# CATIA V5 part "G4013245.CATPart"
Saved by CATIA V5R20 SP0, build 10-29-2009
Part number: G4013245
Revision: 6
Definition: design
Nomenclature: G4013245
Source: made
Description: NOT SPECIFIED
Bounding box of the stored display mesh (mm): x 0 to 45, y -22.5 to 22.5, z -22.5 to 22.5
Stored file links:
  C:\Users\Raffaele\Desktop\3D X SITO CF\BOLEX\25-BUSH REF 401\G4013245.CATPart
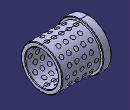
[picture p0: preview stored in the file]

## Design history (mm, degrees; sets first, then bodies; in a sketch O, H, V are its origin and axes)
Body1 "MANIFOLD_SOLID_BREP #10377" (main body)
  Solid1: solid without history
Body2 "MANIFOLD_SOLID_BREP #10526"
  Solid2: solid without history
Body3 "MANIFOLD_SOLID_BREP #10675"
  Solid3: solid without history
Body4 "MANIFOLD_SOLID_BREP #10824"
  Solid4: solid without history
Body5 "MANIFOLD_SOLID_BREP #10973"
  Solid5: solid without history
Body6 "MANIFOLD_SOLID_BREP #11122"
  Solid6: solid without history
Body7 "MANIFOLD_SOLID_BREP #11271"
  Solid7: solid without history
Body8 "MANIFOLD_SOLID_BREP #11420"
  Solid8: solid without history
Body9 "MANIFOLD_SOLID_BREP #11569"
  Solid9: solid without history
Body10 "MANIFOLD_SOLID_BREP #11718"
  Solid10: solid without history
Body11 "MANIFOLD_SOLID_BREP #11867"
  Solid11: solid without history
Body12 "MANIFOLD_SOLID_BREP #12016"
  Solid12: solid without history
Body13 "MANIFOLD_SOLID_BREP #12165"
  Solid13: solid without history
Body14 "MANIFOLD_SOLID_BREP #12314"
  Solid14: solid without history
Body15 "MANIFOLD_SOLID_BREP #12463"
  Solid15: solid without history
Body16 "MANIFOLD_SOLID_BREP #12612"
  Solid16: solid without history
Body17 "MANIFOLD_SOLID_BREP #12761"
  Solid17: solid without history
Body18 "MANIFOLD_SOLID_BREP #12910"
  Solid18: solid without history
Body19 "MANIFOLD_SOLID_BREP #13059"
  Solid19: solid without history
Body20 "MANIFOLD_SOLID_BREP #13208"
  Solid20: solid without history
Body21 "MANIFOLD_SOLID_BREP #13357"
  Solid21: solid without history
Body22 "MANIFOLD_SOLID_BREP #13506"
  Solid22: solid without history
Body23 "MANIFOLD_SOLID_BREP #13655"
  Solid23: solid without history
Body24 "MANIFOLD_SOLID_BREP #13804"
  Solid24: solid without history
Body25 "MANIFOLD_SOLID_BREP #13953"
  Solid25: solid without history
Body26 "MANIFOLD_SOLID_BREP #14102"
  Solid26: solid without history
Body27 "MANIFOLD_SOLID_BREP #14251"
  Solid27: solid without history
Body28 "MANIFOLD_SOLID_BREP #14400"
  Solid28: solid without history
Body29 "MANIFOLD_SOLID_BREP #14549"
  Solid29: solid without history
Body30 "MANIFOLD_SOLID_BREP #14698"
  Solid30: solid without history
Body31 "MANIFOLD_SOLID_BREP #14847"
  Solid31: solid without history
Body32 "MANIFOLD_SOLID_BREP #14996"
  Solid32: solid without history
Body33 "MANIFOLD_SOLID_BREP #15145"
  Solid33: solid without history
Body34 "MANIFOLD_SOLID_BREP #15294"
  Solid34: solid without history
Body35 "MANIFOLD_SOLID_BREP #15443"
  Solid35: solid without history
Body36 "MANIFOLD_SOLID_BREP #15592"
  Solid36: solid without history
Body37 "MANIFOLD_SOLID_BREP #15741"
  Solid37: solid without history
Body38 "MANIFOLD_SOLID_BREP #15890"
  Solid38: solid without history
Body39 "MANIFOLD_SOLID_BREP #16039"
  Solid39: solid without history
Body40 "MANIFOLD_SOLID_BREP #16188"
  Solid40: solid without history
Body41 "MANIFOLD_SOLID_BREP #16337"
  Solid41: solid without history
Body42 "MANIFOLD_SOLID_BREP #16486"
  Solid42: solid without history
Body43 "MANIFOLD_SOLID_BREP #16635"
  Solid43: solid without history
Body44 "MANIFOLD_SOLID_BREP #16784"
  Solid44: solid without history
Body45 "MANIFOLD_SOLID_BREP #16933"
  Solid45: solid without history
Body46 "MANIFOLD_SOLID_BREP #17082"
  Solid46: solid without history
Body47 "MANIFOLD_SOLID_BREP #17231"
  Solid47: solid without history
Body48 "MANIFOLD_SOLID_BREP #17380"
  Solid48: solid without history
Body49 "MANIFOLD_SOLID_BREP #17529"
  Solid49: solid without history
Body50 "MANIFOLD_SOLID_BREP #17678"
  Solid50: solid without history
Body51 "MANIFOLD_SOLID_BREP #17827"
  Solid51: solid without history
Body52 "MANIFOLD_SOLID_BREP #17976"
  Solid52: solid without history
Body53 "MANIFOLD_SOLID_BREP #18125"
  Solid53: solid without history
Body54 "MANIFOLD_SOLID_BREP #18274"
  Solid54: solid without history
Body55 "MANIFOLD_SOLID_BREP #18423"
  Solid55: solid without history
Body56 "MANIFOLD_SOLID_BREP #18572"
  Solid56: solid without history
Body57 "MANIFOLD_SOLID_BREP #18721"
  Solid57: solid without history
Body58 "MANIFOLD_SOLID_BREP #18870"
  Solid58: solid without history
Body59 "MANIFOLD_SOLID_BREP #19019"
  Solid59: solid without history
Body60 "MANIFOLD_SOLID_BREP #19168"
  Solid60: solid without history
Body61 "MANIFOLD_SOLID_BREP #19317"
  Solid61: solid without history
Body62 "MANIFOLD_SOLID_BREP #19466"
  Solid62: solid without history
Body63 "MANIFOLD_SOLID_BREP #19615"
  Solid63: solid without history
Body64 "MANIFOLD_SOLID_BREP #19764"
  Solid64: solid without history
Body65 "MANIFOLD_SOLID_BREP #19913"
  Solid65: solid without history
Body66 "MANIFOLD_SOLID_BREP #20062"
  Solid66: solid without history
Body67 "MANIFOLD_SOLID_BREP #20211"
  Solid67: solid without history
Body68 "MANIFOLD_SOLID_BREP #20360"
  Solid68: solid without history
Body69 "MANIFOLD_SOLID_BREP #20509"
  Solid69: solid without history
Body70 "MANIFOLD_SOLID_BREP #20658"
  Solid70: solid without history
Body71 "MANIFOLD_SOLID_BREP #20807"
  Solid71: solid without history
Body72 "MANIFOLD_SOLID_BREP #20956"
  Solid72: solid without history
Body73 "MANIFOLD_SOLID_BREP #21105"
  Solid73: solid without history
